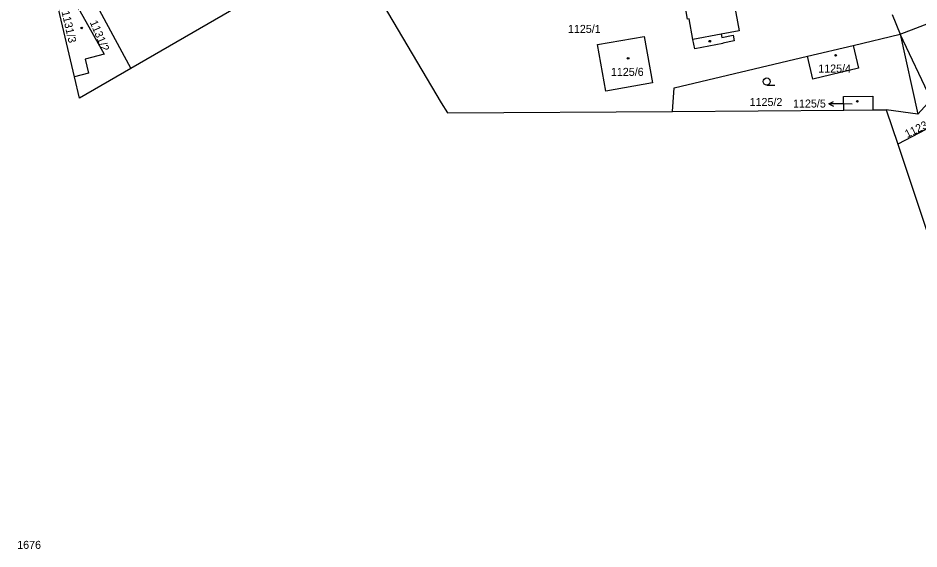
# Model space of a CAD drawing. Extents: x -724107 to -720612, y -1045267 to -1038441.
# Drawn here: x -722328.2 to -722136.9, y -1044251.1 to -1044138.4 of the extents above; entities that cross this region are included whole.
import ezdxf

# ---------------------------------------------------------------- set-up
doc = ezdxf.new("R2010")
doc.units = 0
for name, color, linetype in [('Hranice parcel', 7, 'Continuous'), ('Parcelní čísla', 7, 'Continuous'), ('Pop  PČ popisy', 7, 'Continuous'), ('Vnitřní kresba', 7, 'Continuous'), ('Značky budov', 7, 'Continuous'), ('Značky kultur', 7, 'Continuous')]:
    doc.layers.add(name, color=color, linetype=linetype)

msp = doc.modelspace()

# ---------------------------------------------------------------- linework, layer by layer
at = {"layer": 'Hranice parcel'}
for p, q in [((-722316.21, -1044150.83), (-722321.05, -1044130.29)), ((-722313.91, -1044131.18), (-722304.27, -1044149.11)), ((-722281.45, -1044135.9), (-722304.27, -1044149.11)), ((-722142.66, -1044137.63), (-722140.94, -1044141.79)), ((-722150.91, -1044144.16), (-722140.94, -1044141.79)), ((-722160.64, -1044146.47), (-722150.91, -1044144.16)), ((-722189.25, -1044158.17), (-722152.93, -1044157.91)), ((-722152.93, -1044157.91), (-722146.74, -1044157.87)), ((-722146.74, -1044157.87), (-722143.89, -1044157.85)), ((-722143.89, -1044157.85), (-722141.46, -1044165.15)), ((-722132.01, -1044160.2), (-722141.46, -1044165.15))]:
    msp.add_line(p, q, dxfattribs=at)
for points in [[(-722178.56, -1044143.8), (-722184.55, -1044144.88), (-722184.92, -1044142.89), (-722185.72, -1044138.56), (-722186.09, -1044138.62), (-722187.12, -1044132.44), (-722183.59, -1044131.85), (-722183.94, -1044129.92), (-722182.77, -1044129.71), (-722183.27, -1044126.93), (-722181.32, -1044126.58), (-722180.82, -1044129.36), (-722177.4, -1044128.75), (-722175.11, -1044141.07), (-722178.93, -1044141.78), (-722178.81, -1044142.46), (-722176.4, -1044142.02), (-722176.18, -1044143.22), (-722178.58, -1044143.67), (-722178.56, -1044143.8)], [(-722140.94, -1044141.79), (-722111.81, -1044130.52), (-722111.38, -1044130.35)], [(-722317.37, -1044132.73), (-722309.92, -1044146.06), (-722313.97, -1044147.09), (-722313.24, -1044150.1), (-722316.21, -1044150.83)], [(-722250.67, -1044135.54), (-722238.4, -1044156.33), (-722237.02, -1044158.51), (-722189.25, -1044158.17)], [(-722205.18, -1044143.96), (-722195.28, -1044142.25), (-722193.51, -1044152.15), (-722203.45, -1044153.89), (-722205.18, -1044143.96)], [(-722140.94, -1044141.79), (-722137.2, -1044158.8), (-722143.89, -1044157.85)], [(-722132.01, -1044160.2), (-722134.38, -1044155.68), (-722140.94, -1044141.79)], [(-722150.91, -1044144.16), (-722149.76, -1044149.02), (-722159.48, -1044151.33), (-722160.64, -1044146.47)], [(-722189.25, -1044158.17), (-722188.91, -1044153.18), (-722160.64, -1044146.47)], [(-722304.27, -1044149.11), (-722315.13, -1044155.4), (-722316.21, -1044150.83)], [(-722152.93, -1044157.91), (-722152.95, -1044155.02), (-722146.76, -1044154.97), (-722146.74, -1044157.87)], [(-722141.46, -1044165.15), (-722130.07, -1044199.35), (-722124.81, -1044197.87)]]:
    msp.add_lwpolyline(points, dxfattribs=at)
at = {"layer": 'Pop  PČ popisy'}
for p, q in [((-722156.07, -1044156.55), (-722155.06, -1044156.06)), ((-722153.07, -1044156.6), (-722156.07, -1044156.55)), ((-722156.07, -1044156.55), (-722155.08, -1044157.07)), ((-722151.15, -1044156.63), (-722153.07, -1044156.6))]:
    msp.add_line(p, q, dxfattribs=at)
at = {"layer": 'Vnitřní kresba'}
for p, q in [((-722178.93, -1044141.78), (-722184.92, -1044142.89)), ((-722137.2, -1044158.8), (-722134.38, -1044155.68))]:
    msp.add_line(p, q, dxfattribs=at)
at = {"layer": 'Značky budov'}
for centre in [(-722314.69, -1044140.47), (-722181.36, -1044143.29), (-722198.7, -1044146.9), (-722154.64, -1044146.28), (-722150.02, -1044156.03)]:
    msp.add_circle(centre, 0.175, dxfattribs=at)
at = {"layer": 'Značky kultur'}
msp.add_line((-722169.27, -1044152.59), (-722167.52, -1044152.59), dxfattribs=at)
msp.add_circle((-722169.27, -1044151.84), 0.75, dxfattribs=at)

# ---------------------------------------------------------------- texts
at = {"layer": 'Parcelní čísla'}
for s, rotation, p in [('1131/3', 283, (-722319, -1044137)), ('1131/2', 293, (-722313.02, -1044139.25)), ('1123/2', 26, (-722139.46, -1044163.85))]:
    msp.add_text(s, height=1.7, rotation=rotation, dxfattribs=at).set_placement(p)
for s, p in [('1125/1', (-722211.47, -1044141.52)), ('1125/6', (-722202.35, -1044150.64)), ('1125/4', (-722158.33, -1044149.94)), ('1125/2', (-722172.9, -1044157.04)), ('1125/5', (-722163.68, -1044157.36)), ('1676', (-722328.39, -1044251.05))]:
    msp.add_text(s, height=1.7, dxfattribs=at).set_placement(p)

doc.saveas('drawing.dxf')
